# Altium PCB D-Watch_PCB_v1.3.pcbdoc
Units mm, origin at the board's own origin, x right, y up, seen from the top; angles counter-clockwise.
Board outline 59.16 x 50.57 mm, 4 copper layers (Top Layer, Inner1, Inner2, Bottom Layer); 66 components, 55 nets, 256 pads, 104 vias.
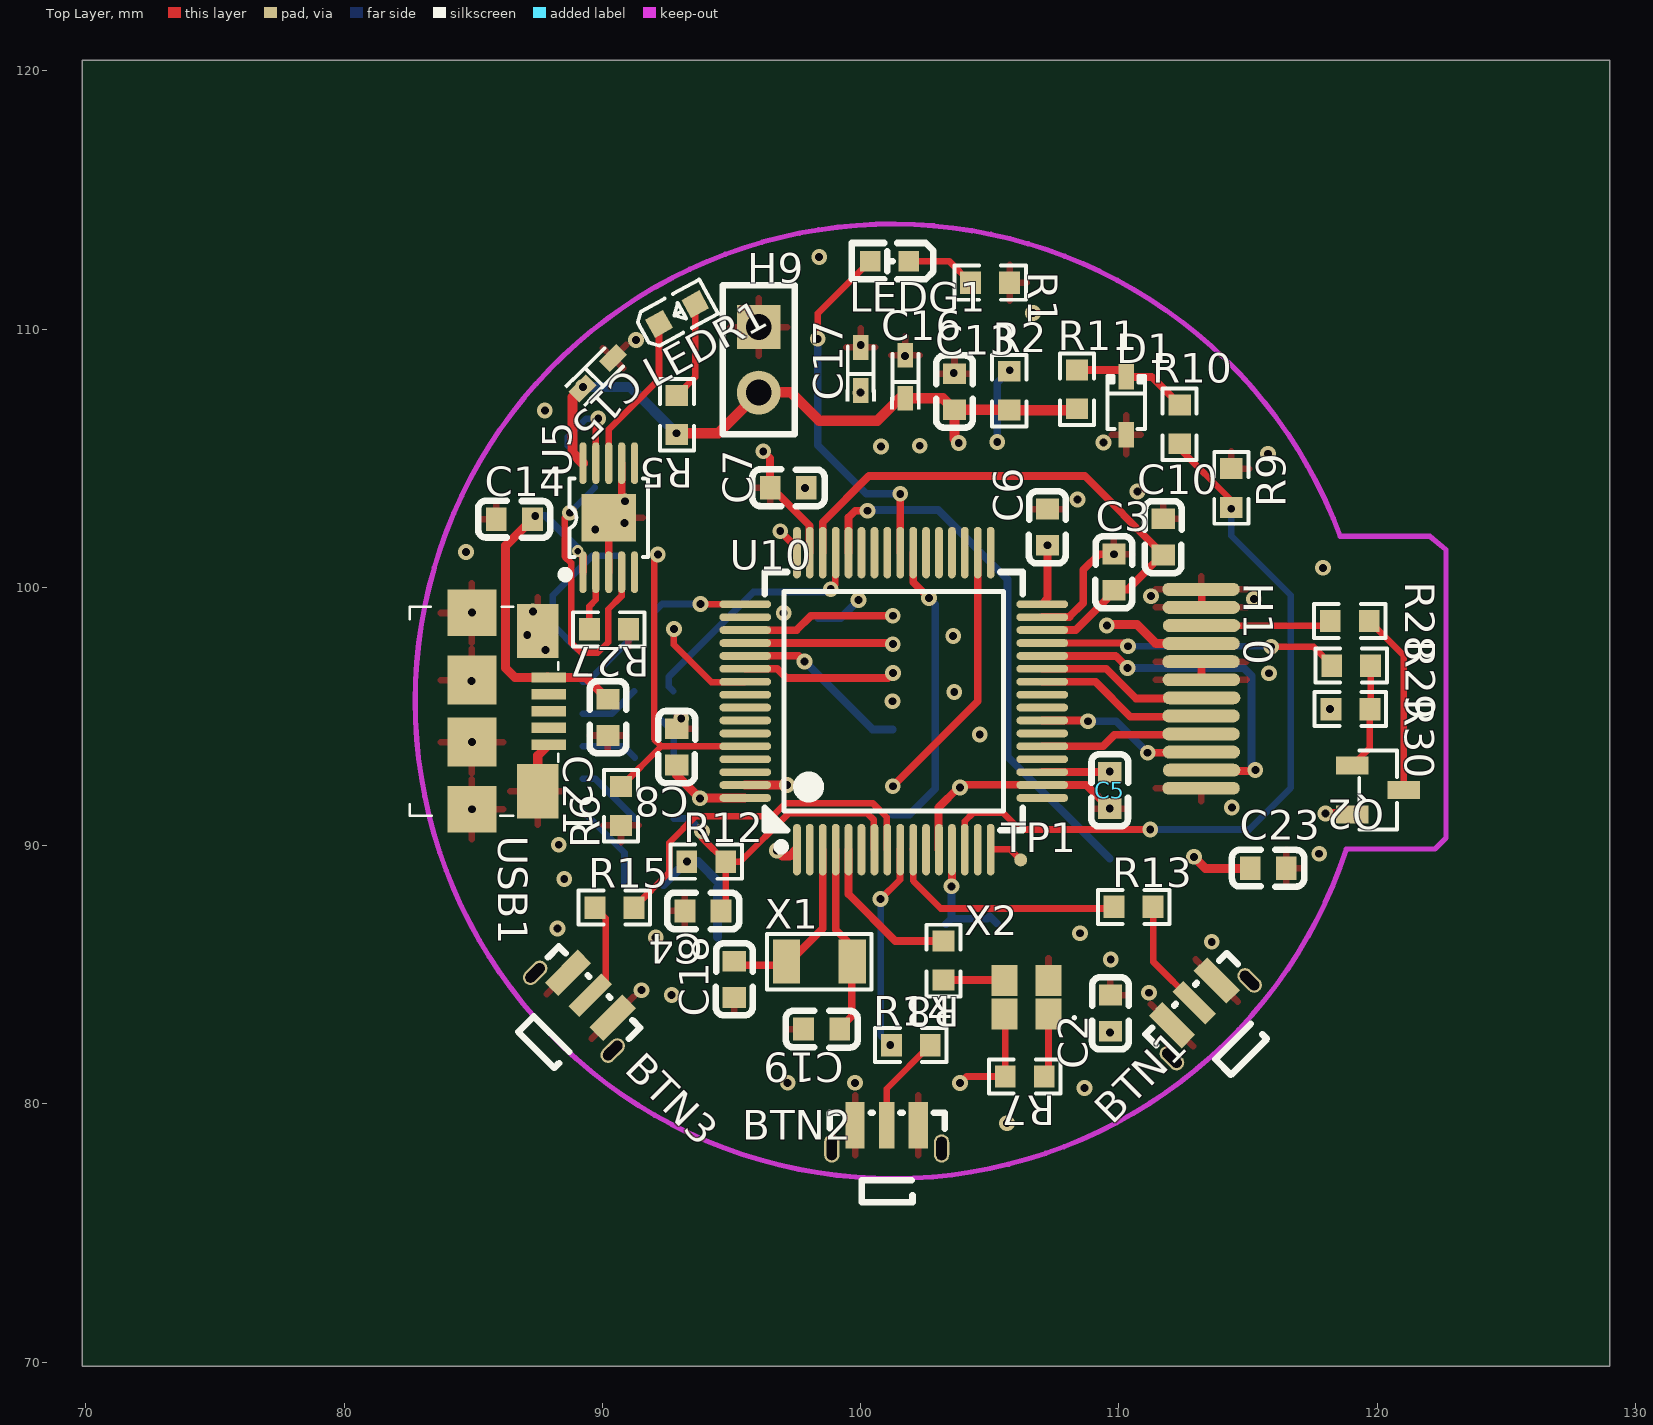
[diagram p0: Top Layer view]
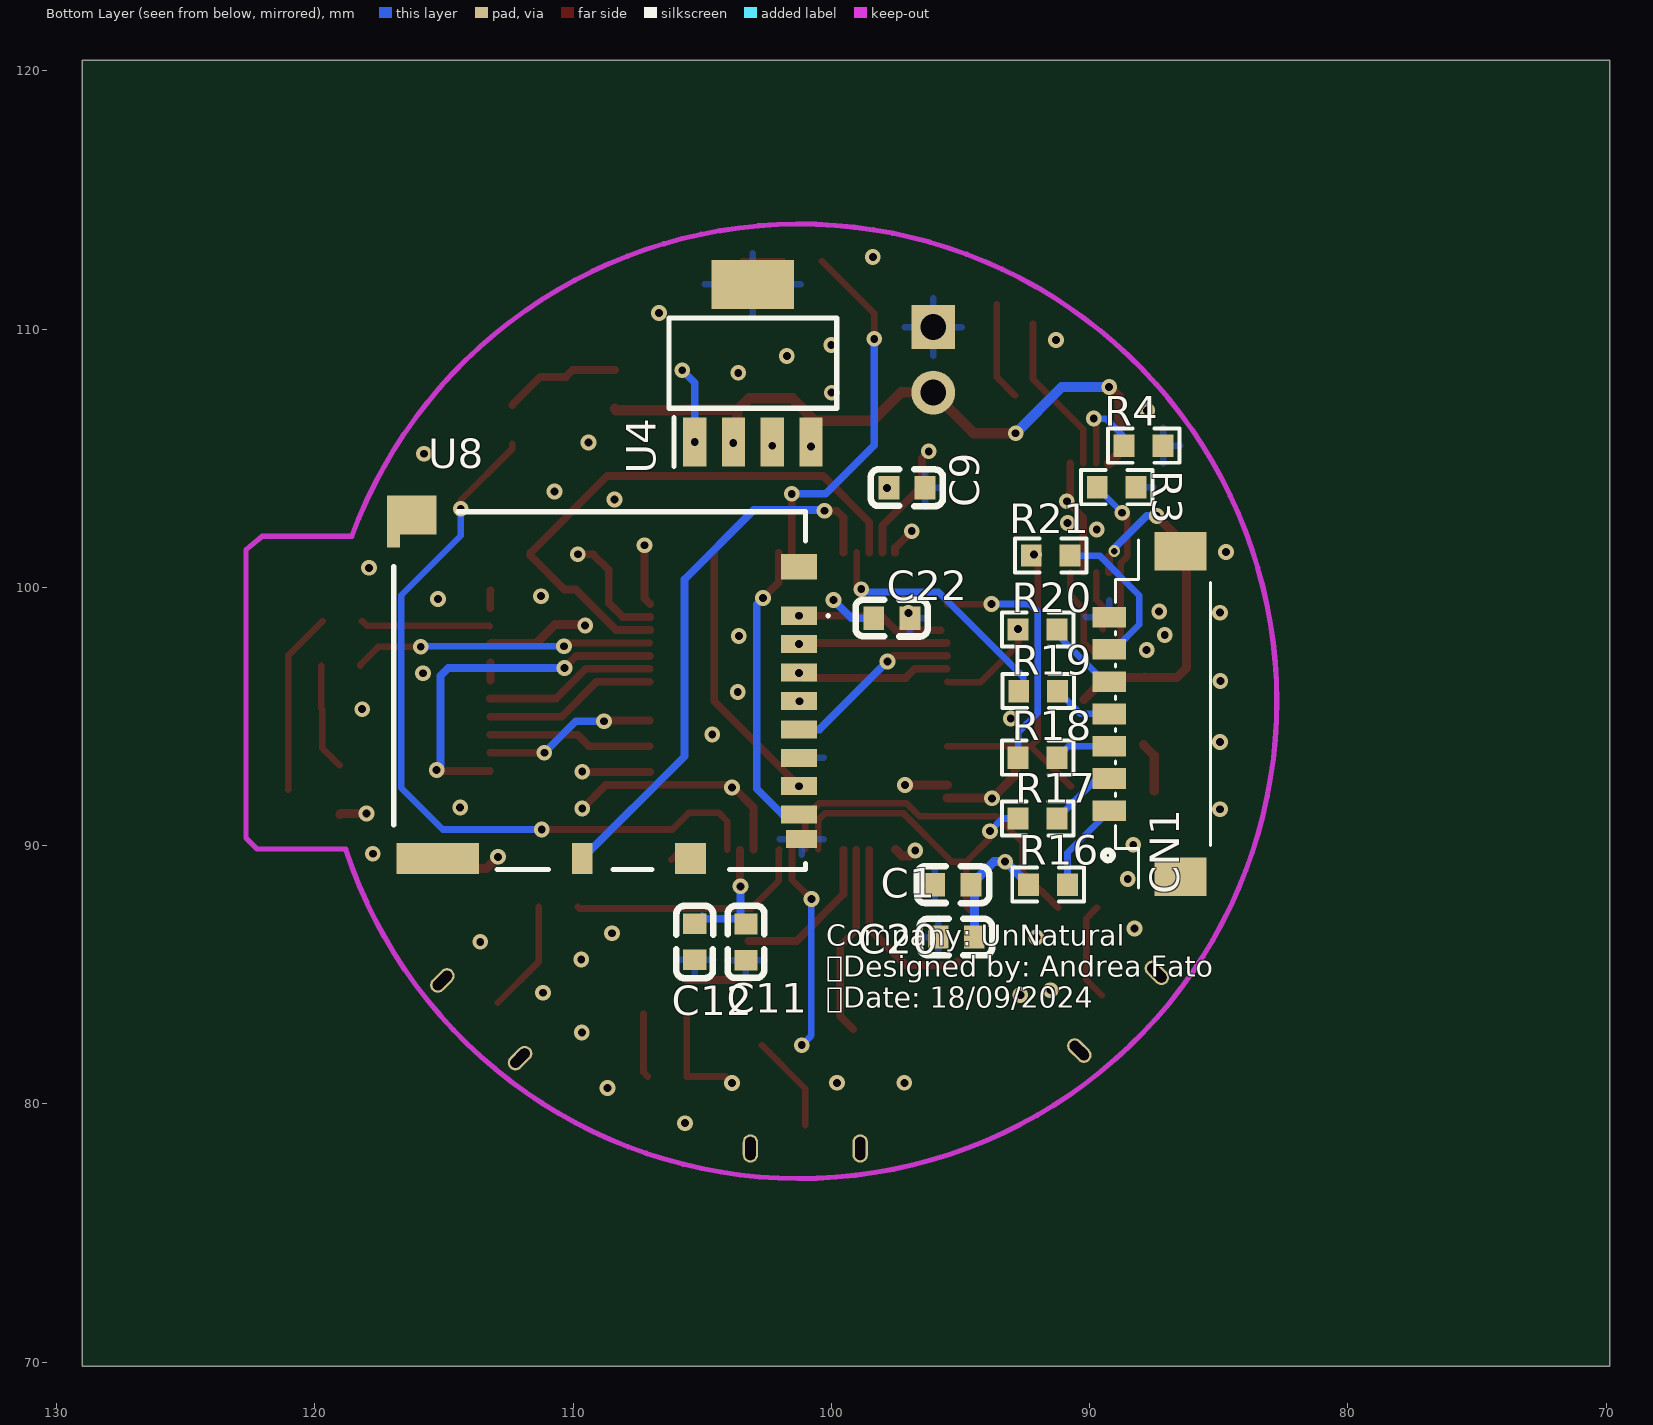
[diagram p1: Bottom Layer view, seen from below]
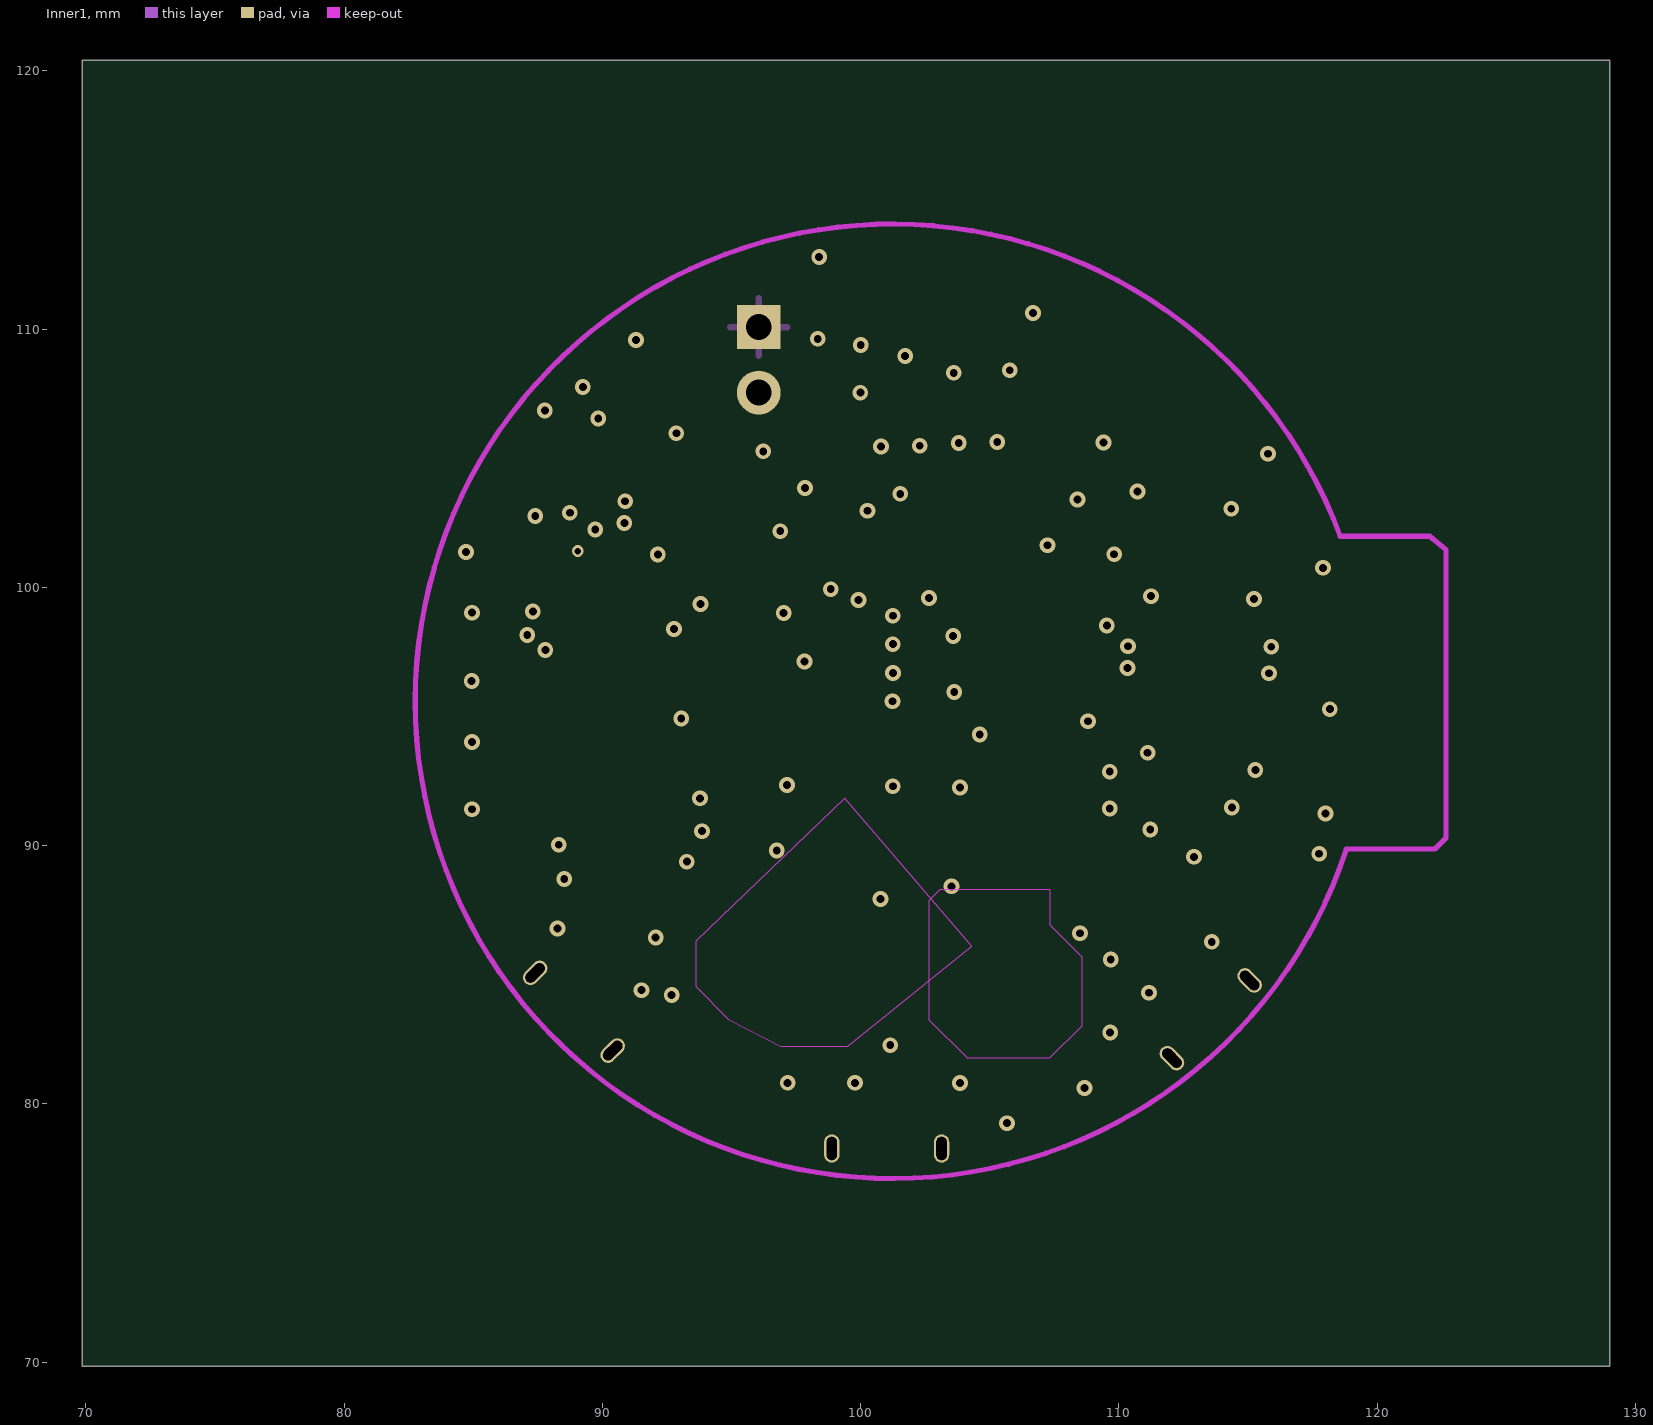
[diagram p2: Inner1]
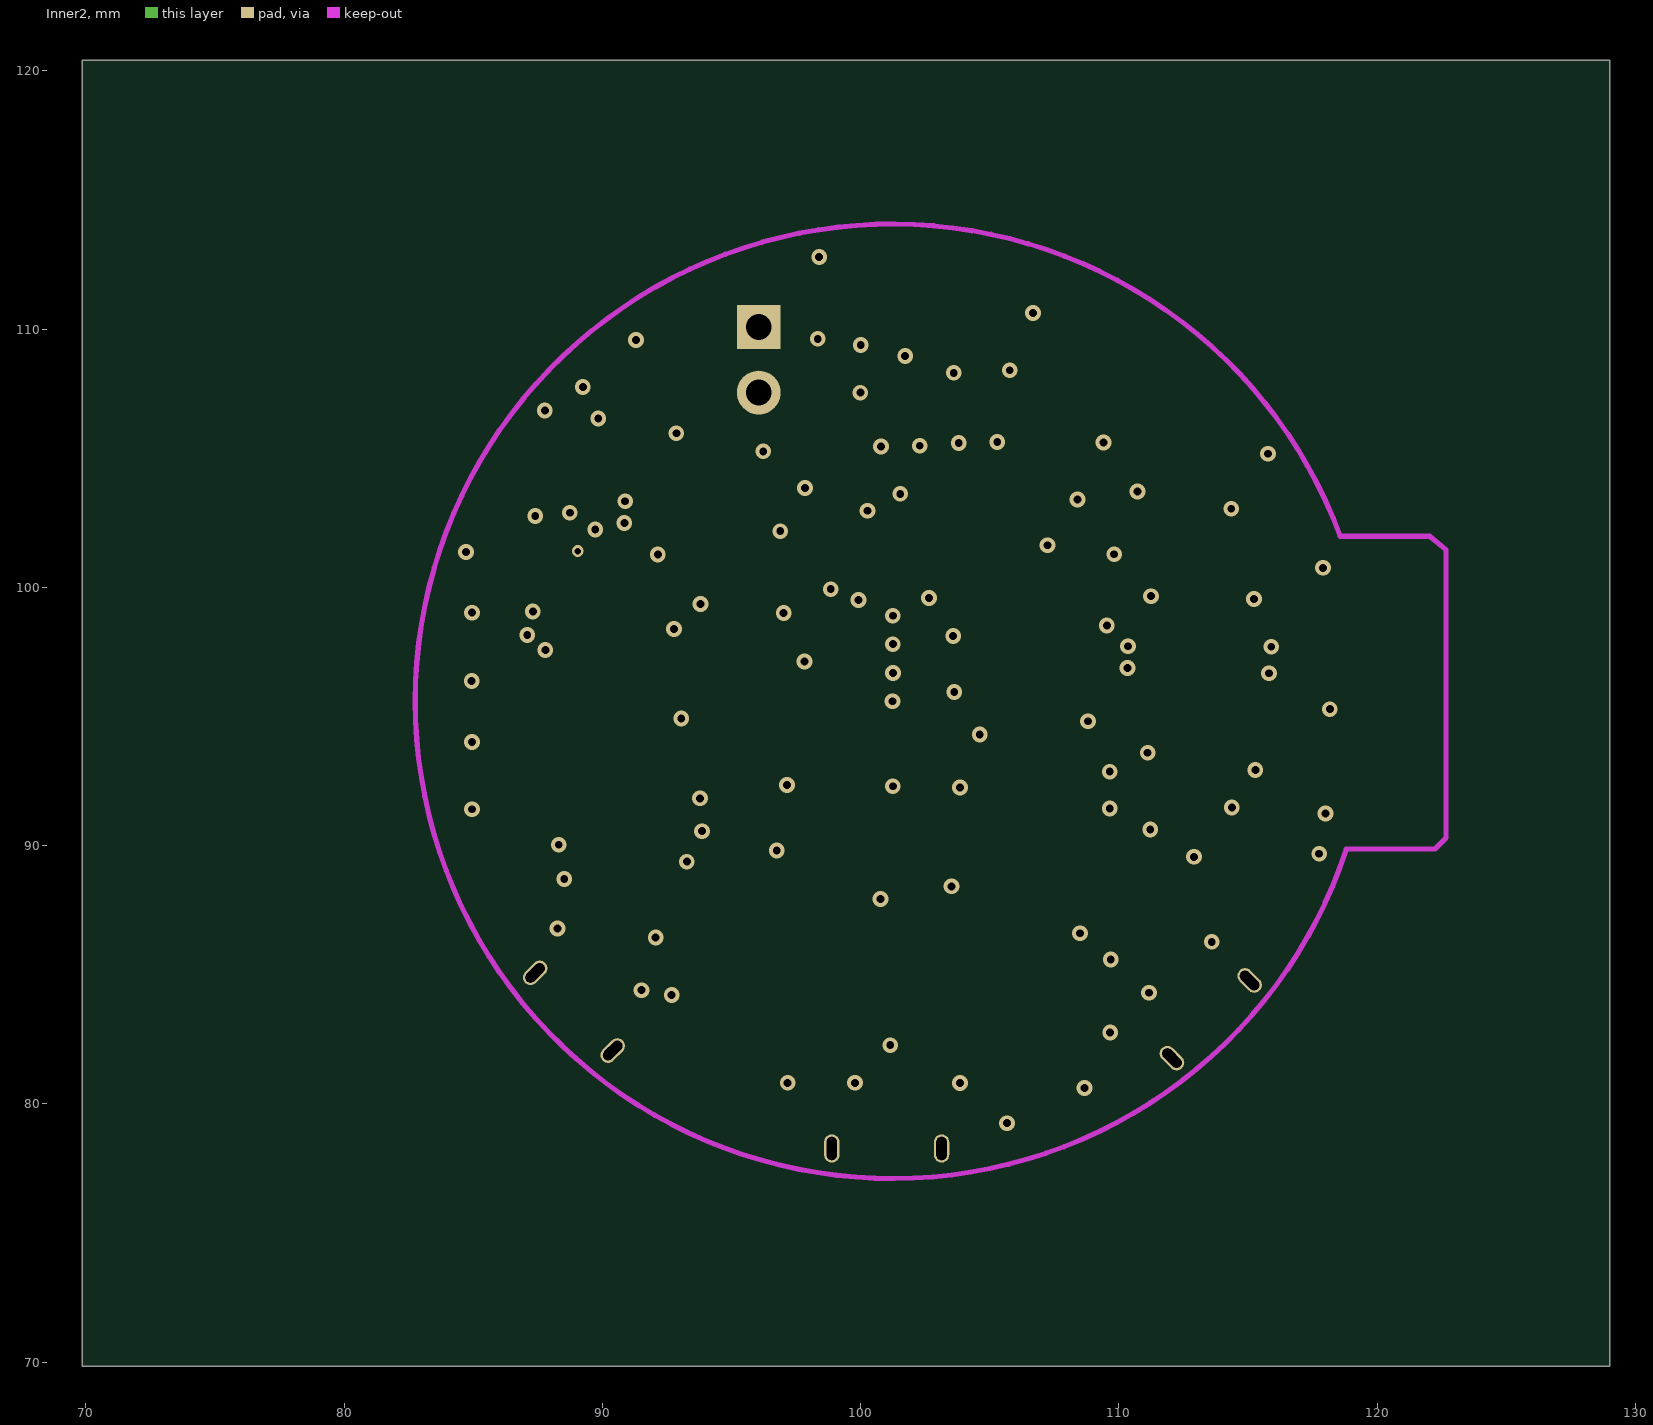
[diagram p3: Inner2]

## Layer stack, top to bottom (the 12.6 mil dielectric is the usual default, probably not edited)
Top Layer: signal copper (thickness not stored)
Dielectric: dielectric 0.32, FR-4, Dk 4.8
Inner1: signal copper (thickness not stored)
Dielectric: dielectric 0.32, FR-4, Dk 4.8
Inner2: signal copper (thickness not stored)
Dielectric: dielectric 0.32, FR-4, Dk 4.8
Bottom Layer: signal copper (thickness not stored)

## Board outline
129.01,69.85 69.85,69.85 69.85,120.418 129.01,120.418

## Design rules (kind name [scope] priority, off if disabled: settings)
Clearance copperThickness1oz [All] p1: gap=0.178 ignorepadtopadclearanceinfootprint=FALSE except(0.01: SMDPad-SMDPad; 0.102: Track-Track; 0.152: Track-SMDPad Track-THPad SMDPad-THPad THPad-THPad Track-Via SMDPad-Via THPad-Via Via-Via Track-Fill SMDPad-Fill THPad-Fill Via-Fill Fill-Fill SMDPad-Region THPad-Region Via-Region Fill-Region Region-Region Track-Poly SMDPad-Poly THPad-Poly Via-Poly Fill-Poly Poly-Poly Track-Text SMDPad-Text THPad-Text Via-Text Fill-Text Region-Text Poly-Text Text-Text; 0.175: Track-Hole SMDPad-Hole THPad-Hole Via-Hole Fill-Hole Region-Hole Poly-Hole Text-Hole Sheet-Hole; 0.3: Track-Region Region-Poly Track-Sheet SMDPad-Sheet THPad-Sheet Via-Sheet Fill-Sheet Region-Sheet Poly-Sheet Text-Sheet)
Clearance copperThickness2oz [All] p1: gap=0.178 ignorepadtopadclearanceinfootprint=FALSE except(0.152: Track-SMDPad SMDPad-SMDPad Track-THPad SMDPad-THPad THPad-THPad Track-Via SMDPad-Via THPad-Via Via-Via SMDPad-Fill THPad-Fill Via-Fill Fill-Fill Track-Region SMDPad-Region THPad-Region Via-Region Region-Region Track-Poly SMDPad-Poly THPad-Poly Via-Poly Fill-Poly Region-Poly Poly-Poly Track-Text SMDPad-Text THPad-Text Via-Text Fill-Text Region-Text Poly-Text Text-Text; 0.175: Track-Hole SMDPad-Hole THPad-Hole Via-Hole Fill-Hole Region-Hole Poly-Hole Text-Hole Sheet-Hole; 0.203: Track-Track; 0.3: Track-Fill Fill-Region Track-Sheet SMDPad-Sheet THPad-Sheet Via-Sheet Fill-Sheet Region-Sheet Poly-Sheet Text-Sheet)
Clearance BGA [All] p1: gap=0.178 ignorepadtopadclearanceinfootprint=FALSE except(0.099: Track-Track Track-SMDPad SMDPad-SMDPad Track-THPad SMDPad-THPad THPad-THPad Track-Via SMDPad-Via THPad-Via Via-Via Track-Fill SMDPad-Fill THPad-Fill Via-Fill Fill-Fill Track-Region SMDPad-Region THPad-Region Via-Region Fill-Region Region-Region Track-Poly SMDPad-Poly THPad-Poly Via-Poly Fill-Poly Region-Poly Poly-Poly Track-Hole SMDPad-Hole THPad-Hole Via-Hole Fill-Hole Region-Hole Poly-Hole Text-Hole Sheet-Hole; 0.152: Track-Text SMDPad-Text THPad-Text Via-Text Fill-Text Region-Text Poly-Text Text-Text; 0.3: Track-Sheet SMDPad-Sheet THPad-Sheet Via-Sheet Fill-Sheet Region-Sheet Poly-Sheet Text-Sheet)
DiffPairsRouting differentialPair [All] p1: maxuncoupledlength=10 maxlimit=5.9843 mostfreqgap=5.9843 toplayer_minwidth=5 toplayer_prefwidth=10 toplayer_maxwidth=100 bottomlayer_minwidth=5 bottomlayer_prefwidth=10 bottomlayer_maxwidth=100 midlayer1_minwidth=5 midlayer1_prefwidth=10 midlayer1_maxwidth=100 midlayer2_minwidth=5 midlayer2_prefwidth=10 midlayer2_maxwidth=100
PasteMaskExpansion pasteMaskExpansion [All] p1:
PlaneConnect innerPlane [All] p1: planeconnectstyle=Relief reliefexpansion=0.508 reliefentries=4 reliefconductorwidth=0.254 reliefairgap=0.254
PolygonConnect copperRegion [All] p1: connectstyle=Relief reliefentries=4 reliefconductorwidth=10 polygonreliefangle="90 Angle" airgapwidth=10
PolygonConnect copperRegionOSC [All] p1: connectstyle=Relief reliefentries=4 reliefconductorwidth=10 polygonreliefangle="90 Angle" airgapwidth=10
RoutingVias viaSize [All] p1: viastyle="Through Hole" holewidth=12.0078 minholewidth=5.9056 maxholewidth=248.0314 width=24.0158 minwidth=9.8426 maxwidth=393.7008
SolderMaskExpansion solderMaskExpansion [All] p1: useseparateexpansions=TRUE expansion=2.0079 expansionbottom=2.0079
Width copperThickness1oz [All] p1: maxlimit=100 minlimit=4 preferedwidth=10
Width copperThickness2oz [All] p1: maxlimit=100 minlimit=8 preferedwidth=10

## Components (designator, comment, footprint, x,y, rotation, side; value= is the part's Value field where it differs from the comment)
BTN1 "436333033816" SW-SMD_436333033816 113.677,83.153 r45 top
BTN2 "436333033816" SW-SMD_436333033816 101.005,78.1 r0 top
BTN3 "436333033816" SW-SMD_436333033816 88.77,83.446 r315 top
C1 "GCJ188R71C104KA01D" C0603 95.29,88.49 r0 bottom
C2 "GCJ188R71C104KA01D" C0603 109.67,83.516 r90 top
C3 "GCJ188R71C104KA01D" C0603 109.803,100.59 r90 top
C4 "GCJ188R71C104KA01D" C0603 93.893,87.474 r180 top
C5 "GCJ188R71C104KA01D" C0603 109.64,92.136 r270 top
C6 "GCJ188R71C104KA01D" C0603 107.228,102.333 r90 top
C7 "GCJ188R71C104KA01D" C0603 97.195,103.857 r180 top
C8 "GCJ188R71C104KA01D" C0603 92.877,93.824 r90 top
C9 "GCJ188C70J475KE02D" C0603 97.068,103.857 r180 bottom
C10 "GCJ188R71C104KA01D" C0603 111.713,101.952 r90 top
C11 "GCJ188R71C104KA01D" C0603 103.306,86.267 r270 bottom
C12 "CC0603KRX7R5BB105" C0603 105.286,86.277 r90 bottom
C13 "CC0603KRX7R5BB105" C0603 103.63,107.576 r270 top
C14 "CC0603KRX7R5BB105" C0603 86.59,102.636 r0 top
C15 "T58MM106M6R3C0300" CAP-SMD_L1.6-W0.8-RD 89.82,108.286 r225 top
C16 "T58MM106M6R3C0300" CAP-SMD_L1.6-W0.8-RD 101.73,108.156 r270 top
C17 "T58MM106M6R3C0300" CAP-SMD_L1.6-W0.8-RD 100,108.456 r270 top
C18 "CAP_0603" C0603 95.104,84.819 r270 top
C19 "CAP_0603" C0603 98.484,82.898 r180 top
C20 "AC0603KRX7R6BB105" C0603 95.163,86.458 r180 bottom
C21 "GCJ188R71C104KA01D" C0603 90.21,94.966 r270 top
C22 "GCJ188R71C104KA01D" C0603 97.655,98.809 r180 bottom
C23 "GCJ188R71C104KA01D" C0603 115.779,89.124 r0 top
CN1 "53398-0771" CONN-SMD_7P-P1.25_53398-0771 87.855,95.099 r90 bottom
D1 "TDZ3V6J,115" SOD-323_L1.7-W1.3-LS2.5-RD-1 110.276,107.032 r270 top
H9 "HDR-F_2.54_1x2P" HDR-TH_2P-P2.54-V-F 96.052,108.81 r270 top
H10 "HDR-M_2.54_1x12P" HDR-TH_12P-P2.54-V-M 113.118,96.046 r270 top
LEDG1 "APT1608MGC" LED-SMD_L1.6-W0.8-RD 101.115,112.634 r180 top
LEDR1 "APT1608SURCK" LED0603-RD 92.89,110.586 r28.78 top
Q2 "NSS40200LT1G" SOT-23-3_L2.9-W1.3-P1.90-LS2.4-BR 120.03,92.156 r180 top
R1 "Res_0603" R0603 105.01,111.797 r180 top
R2 "Res_0603" R0603 105.75,107.616 r90 top
R3 "Res_0603" R0603 88.95,103.879 r0 bottom
R4 "Res_0603" R0603 87.907,105.487 r180 bottom
R5 "Res_0603" R0603 92.881,106.678 r90 top
R6 "Res_0603" R0603 90.718,91.538 r90 top
R7 "Res_0603" R0603 106.35,81.063 r180 top
R8 "Res_0603" R0603 103.207,85.553 r90 top
R9 "Res_0603" R0603 114.349,103.848 r90 top
R10 "Res_0603" R0603 112.347,106.311 r90 top
R11 "Res_0603" R0603 108.371,107.667 r270 top
R12 "Res_0603" R0603 94.02,89.379 r0 top
R13 "Res_0603" R0603 110.566,87.629 r180 top
R14 "Res_0603" R0603 101.94,82.276 r180 top
R15 "Res_0603" R0603 90.464,87.601 r0 top
R16 "Res_0603" R0603 91.607,88.49 r180 bottom
R17 "Res_0603" R0603 92.012,91.051 r180 bottom
R18 "Res_0603" R0603 92.012,93.405 r180 bottom
R19 "Res_0603" R0603 91.988,95.983 r180 bottom
R20 "Res_0603" R0603 92.012,98.368 r180 bottom
R21 "Res_0603" R0603 91.504,101.231 r180 bottom
R27 "Res_0603" R0603 90.25,98.376 r180 top
R28 "Res_0603" R0603 118.935,98.695 r180 top
R29 "Res_0603" R0603 118.99,96.972 r180 top
R30 "Res_0603" R0603 118.96,95.286 r0 top
TP1 "Test-Point" Test-Point-0.5mm 106.194,89.448 r0 top
U4 "LP3874EMP-3.3_NOPB_" SOT150P700X180-5N 103.037,108.683 r90 bottom
U5 "BQ24092DGQR" MSOP-10_L3.0-W3.0-P0.50-LS5.0-BL-EP 90.244,102.699 r0 top
U8 "DM3BT-DSF-PEJS_" DM3BTDSFPEJS 108.869,96.227 r270 bottom
U10 "STM32H7B0RBT6" LQFP-64_L10.0-W10.0-P0.50-LS12.0-BL 101.28,95.596 r0 top
USB1 "10118192-0001LF" MICRO-USB-SMD_10118192-0001LF_1 86.432,95.209 r270 top
X1 "NX3215SA-32.768K-STD-MUA-9" CRYSTAL-SMD_L3.2-W1.5-1 98.395,85.507 r0 top
X2 "EC5625ETTTS-25.000M_TR_" EC5625ETTTS25000MTR 106.42,84.136 r180 top

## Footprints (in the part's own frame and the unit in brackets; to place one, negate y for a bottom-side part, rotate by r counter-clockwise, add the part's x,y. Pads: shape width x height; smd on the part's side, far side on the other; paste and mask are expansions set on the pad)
C0603 [mm]
  rect 0.8x0.9 smd: 1(-0.7,0) 2(0.7,0)
  silkscreen extent -1.41,-0.71 1.39,0.72
CAP-SMD_L1.6-W0.8-RD [mm]
  rect 0.954x0.594 smd: 1(0.835,0) 2(-0.835,0)
  silkscreen extent -0.88,-0.58 1.26,0.58
CONN-SMD_7P-P1.25_53398-0771 [mm]
  rect 0.8x1.3 smd: 1(-3.75,1.375) 2(-2.5,1.375) 3(-1.25,1.375) 4(0,1.375) 5(1.25,1.375) 6(2.5,1.375) 7(3.75,1.375)
  rect 1.5x2 smd: 8(6.3,-1.375) 9(-6.3,-1.375)
  silkscreen extent -6.73,-2.54 6.73,1.61
CRYSTAL-SMD_L3.2-W1.5-1 [mm]
  rect 1.05x1.7 smd: 1(-1.275,0) 2(1.275,0)
  silkscreen extent -2.03,-1.08 2.03,1.08
DM3BTDSFPEJS [mm]
  rect 0.7x1.4 smd: 1(-2.675,7.625) 2(-1.575,7.625) 3(-0.475,7.625) 4(0.625,7.625) 5(1.725,7.625) 6(2.825,7.625) 7(3.925,7.625) 8(5.025,7.625)
  rect 1.2x0.8 smd: 9(6.725,-0.775)
  rect 0.7x1.2 smd: 10(5.975,7.725)
  rect 1x1.4 smd: 11(-4.575,7.625)
  rect 1.2x1.2 smd: 12(6.725,3.425)
  rect 1.2x3.2 smd: 13(6.725,-6.375)
  rect 1.5x1.9 smd: 14(-6.575,-7.375)
  rect 0.5x0.5 smd: 15(-5.575,-8.075)
  silkscreen extent -6.7,-8.07 7.15,8.8
EC5625ETTTS25000MTR [mm]
  rect 1x1.2 smd: 1(-0.85,0.65) 2(-0.85,-0.65) 3(0.85,-0.65) 4(0.85,0.65)
  silkscreen extent -1.9,0.75 -1.8,0.85
HDR-TH_2P-P2.54-V-F [mm]
  rect 1.7x1.7 hole 1: 1(-1.27,0)
  round 1.7 hole 1: 2(1.27,0)
  silkscreen extent -2.88,-1.39 2.88,1.4
HDR-TH_12P-P2.54-V-M [mm]
  oval 0.5x3 smd: 1(-3.877,0.059) 2(-3.177,0.069) 3(-2.477,0.079) 4(-1.777,0.059) 5(-1.077,0.059) 6(-0.377,0.069) 7(0.323,0.079) 8(1.023,0.059) 9(1.723,0.059) 10(2.423,0.069) 11(3.123,0.079) 12(3.823,0.059)
LED0603-RD [mm]
  rect 0.8x0.8 smd: 1(-0.799,0) 2(0.799,0)
  silkscreen extent -1.49,-0.75 1.39,0.76
LED-SMD_L1.6-W0.8-RD [mm]
  rect 0.8x0.8 smd: 1(-0.75,0) 2(0.75,0)
  silkscreen extent -1.7,-0.7 1.47,0.7
LQFP-64_L10.0-W10.0-P0.50-LS12.0-BL [mm]
  oval 0.3x2 smd: 1(-3.75,-5.75) 2(-3.25,-5.75) 3(-2.75,-5.75) 4(-2.25,-5.75) 5(-1.75,-5.75) 6(-1.25,-5.75) 7(-0.75,-5.75) 8(-0.25,-5.75) 9(0.25,-5.75) 10(0.75,-5.75) 11(1.25,-5.75) 12(1.75,-5.75) 13(2.25,-5.75) 14(2.75,-5.75) 15(3.25,-5.75) 16(3.75,-5.75) 33(3.75,5.75) 34(3.25,5.75) 35(2.75,5.75) 36(2.25,5.75) 37(1.75,5.75) 38(1.25,5.75) 39(0.75,5.75) 40(0.25,5.75) 41(-0.25,5.75) 42(-0.75,5.75) 43(-1.25,5.75) 44(-1.75,5.75) 45(-2.25,5.75) 46(-2.75,5.75) 47(-3.25,5.75) 48(-3.75,5.75)
  oval 2x0.3 smd: 17(5.75,-3.75) 18(5.75,-3.25) 19(5.75,-2.75) 20(5.75,-2.25) 21(5.75,-1.75) 22(5.75,-1.25) 23(5.75,-0.75) 24(5.75,-0.25) 25(5.75,0.25) 26(5.75,0.75) 27(5.75,1.25) 28(5.75,1.75) 29(5.75,2.25) 30(5.75,2.75) 31(5.75,3.25) 32(5.75,3.75) 49(-5.75,3.75) 50(-5.75,3.25) 51(-5.75,2.75) 52(-5.75,2.25) 53(-5.75,1.75) 54(-5.75,1.25) 55(-5.75,0.75) 56(-5.75,0.25) 57(-5.75,-0.25) 58(-5.75,-0.75) 59(-5.75,-1.25) 60(-5.75,-1.75) 61(-5.75,-2.25) 62(-5.75,-2.75) 63(-5.75,-3.25) 64(-5.75,-3.75)
  silkscreen extent -5,-5.79 5,5
MICRO-USB-SMD_10118192-0001LF_1 [mm]
  rect 0.4x1.35 smd: 1(-1.3,1.487) 2(-0.65,1.487) 3(0,1.487) 4(0.65,1.487) 5(1.3,1.487)
  rect 1.8x1.9 smd: 6(-3.8,-1.487) 6(3.8,-1.487)
  rect 2.1x1.6 smd: 6(-3.1,1.063) 6(3.1,1.063)
  rect 1.9x1.9 smd: 6(-1.199,-1.487) 6(1.199,-1.487)
  silkscreen extent -4.05,-3.89 4.05,1.86
MSOP-10_L3.0-W3.0-P0.50-LS5.0-BL-EP [mm]
  oval 0.28x1.62 smd: 1(-1,-2.11) 2(-0.5,-2.11) 3(0,-2.11) 4(0.5,-2.11) 5(1,-2.11) 6(1,2.11) 7(0.5,2.11) 8(0,2.11) 9(-0.5,2.11) 10(-1,2.11)
  rect 2.1x1.83 smd: 11(0,0)
  silkscreen extent -1.84,-2.35 1.52,1.52
R0603 [mm]
  rect 0.806x0.864 smd: 1(-0.753,0) 2(0.753,0)
  silkscreen extent -1.39,-0.66 1.39,0.66
SOD-323_L1.7-W1.3-LS2.5-RD-1 [mm]
  rect 0.985x0.6 smd: 1(-1.118,0) 2(1.118,0)
  silkscreen extent -1.15,-0.73 0.9,0.73
SOT150P700X180-5N [mm]
  rect 1.9x0.9 smd: 1(-3.05,2.25) 2(-3.05,0.75) 3(-3.05,-0.75) 4(-3.05,-2.25)
  rect 1.9x3.2 smd: 5(3.05,0)
  silkscreen extent -4,-3.25 1.75,3.25
SOT-23-3_L2.9-W1.3-P1.90-LS2.4-BR [mm]
  rect 1.25x0.7 smd: 1(1,-0.95) 2(1,0.95) 3(-1,0)
  silkscreen extent -0.73,-1.53 0.73,1.53
SW-SMD_436333033816 [mm]
  rect 0.75x1.8 smd: 1(-1.225,1.075) 3(1.225,1.075)
  rect 0.6x1.8 smd: 2(0,1.075)
  oval 0.6x1.1 hole 0.4 slot 0.9 at 90 deg: 6(-2.125,0.175) 6(2.125,0.175)
  silkscreen extent -2.2,-1.9 2.25,1.55
Test-Point-0.5mm [mm]
  round 0.5 smd: 1(0,0)

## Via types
v1: diameter 0.61, hole 0.305, Top Layer to Bottom Layer, 103 vias
v2: diameter 0.45, hole 0.25, Top Layer to Bottom Layer, 1 vias

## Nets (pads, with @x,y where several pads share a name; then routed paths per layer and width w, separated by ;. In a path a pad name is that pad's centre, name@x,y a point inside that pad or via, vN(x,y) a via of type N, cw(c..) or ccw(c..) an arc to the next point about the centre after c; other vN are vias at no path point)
5V_USB_CHGR: C14.2 C21.1 U5.1 USB1.1 | length 14
  Top Layer w0.3: v2(89.038,101.407) 89.244,101.201 U5.1
  Top Layer w0.35: v1(87.396,102.762) 86.25,101.616 86.25,96.876 86.617,96.509 87.858,96.509 USB1.1@87.87,96.521 ; USB1.1 89.367,96.509 C21.1
  Bottom Layer w0.3: v1(87.396,102.762) 87.41,102.776 87.78,102.776 89.038,101.518 v2(89.038,101.407)
$1N5489: R2.2 U4.1 | length 3
  Bottom Layer w0.3: v1(105.287,105.633) 105.287,107.926 v1(105.77,108.409)
$1N5967: R3.2 U5.4 | length 11.3
  Top Layer w0.254: v1(88.737,102.89) 88.534,102.687 88.534,101.198 88.788,100.944 88.788,97.855 89.177,97.466 89.816,97.466 90.224,97.874 90.224,99.15 90.74,99.666 90.74,100.585 U5.4
  Bottom Layer w0.254: v1(88.737,102.89) 89.704,103.857 R3.2
$1N5968: R27.2 U5.2 | length 2.3
  Top Layer w0.254: R27.2 89.497,99.272 89.744,99.52 U5.2
$1N5969: R4.1 U5.9 | length 3.6
  Top Layer w0.254: U5.9 89.744,106.443 v1(89.837,106.536)
  Bottom Layer w0.254: R4.1 88.661,105.826 89.37,106.536 v1(89.837,106.536)
$1N5973: LEDR1.1 U5.8 | length 6.2
  Top Layer w0.254: U5.8 90.244,106.117 92.189,108.062 LEDR1.1
$1N5974: LEDR1.2 R5.2 | length 3.8
  Top Layer w0.254: R5.2 93.591,108.141 LEDR1.2
$1N21382: LEDG1.1 R1.2 | length 2.7
  Top Layer w0.254: LEDG1.1 103.42,112.634 R1.2
$2N8217: R7.1 X2.1 | length 2.5
  Top Layer w0.254: R7.1 107.27,81.229 X2.1
$2N8264: R8.1 X2.3 | length 2.4
  Top Layer w0.3: R8.1 105.557,84.799 X2.3
$2N18890: D1.1 R10.2 R11.1 | length 4.5
  Top Layer w0.3: R11.1 110.005,108.42 D1.1 111.262,108.15 R10.2
$2N23973: TP1.1 U10.16 | length 1.4
  Top Layer w0.254: U10.16@105.009,89.852 105.789,89.852 TP1.1
$3N1058: CN1.1 R16.2 | length 3.5
  Bottom Layer w0.254: CN1.1 90.854,89.725 R16.2
$3N1061: CN1.2 R17.2 | length 2.7
  Bottom Layer w0.254: CN1.2 89.711,92.599 R17.2
$3N1065: CN1.3 R18.2 | length 2.2
  Bottom Layer w0.254: CN1.3 90.815,93.849 R18.2
$3N1094: CN1.4 R19.2 | length 2.4
  Bottom Layer w0.254: CN1.4 90.35,95.099 R19.2
$3N1097: CN1.5 R20.2 | length 3
  Bottom Layer w0.254: CN1.5 89.425,96.349 91.259,98.182 R20.2
$3N1126: CN1.6 R21.2 | length 6
  Bottom Layer w0.254: CN1.6 89.036,97.599 88.08,98.554 88.08,99.696 89.615,101.231 R21.2
$3N2256: BTN2.2 R14.1 | length 3.8
  Top Layer w0.254: BTN2.2 101.005,80.588 R14.1
$3N2358: BTN3.2 R15.1 | length 3.8
  Top Layer w0.254: BTN3.2 90.13,84.806 90.13,87.182 R15.1
$3N11256: BTN1.2 R13.1 | length 4.4
  Top Layer w0.254: R13.1 111.319,85.511 BTN1.2
$3N22100: H10.3 R28.2 | length 5
  Top Layer w0.254: H10.3@113.219,98.493 113.239,98.513 117.979,98.513 118.162,98.695 R28.2
$3N22908: Q2.1 R29.1 R30.2 | length 4.2
  Top Layer w0.254: Q2.1 119.713,93.789 R30.2 119.743,95.316 R29.1
$3N22933: Q2.3 R28.1 | length 7.1
  Top Layer w0.254: R28.1 121.03,97.354 Q2.3
+3V3: 
ADC1_IN16: R9.1 R10.1 U10.14 | length 29.9
  Top Layer w0.254: U10.14 104.03,90.946 104.35,91.266 105.52,91.266 106.16,90.626 v1(111.21,90.626) ; R10.1 112.347,105.374 114.349,103.372 v1(114.349,103.045)
  Bottom Layer w0.254: v1(111.21,90.626) 115.04,90.626 116.65,92.236 116.65,99.696 114.349,101.997 v1(114.349,103.045)
BOOT0: R6.2 R21.1 U10.60 | length 13
  Top Layer w0.254: R6.2 92.279,93.852 ; v1(92.144,101.271) 92,101.127 92,94.131 92.279,93.852 ; U10.60@95.509,93.852 93.45,93.852 93.443,93.845 92.312,93.845 92.305,93.852 92.279,93.852
GC9A01_BL: R29.2 U10.29 | length 11.6
  Top Layer w0.254: U10.29 110.227,97.846 v1(110.353,97.719) ; v1(115.894,97.702) 117.533,97.702 118.237,96.999 R29.2
  Bottom Layer w0.254: v1(110.353,97.719) 115.877,97.719 v1(115.894,97.702)
GC9A01_CS: H10.8 U10.26 | length 6.7
  Top Layer w0.3: U10.26 109.09,96.346 110.443,94.993 H10.8@113.199,94.993
GC9A01_DC: H10.7 U10.27 | length 6.7
  Top Layer w0.3: U10.27 109.51,96.846 110.663,95.693 H10.7@113.219,95.693
GC9A01_RST: H10.11 U10.28 | length 14.2
  Top Layer w0.3: U10.28 109.868,97.346 v1(110.334,96.88) ; H10.11@113.219,92.893 115.239,92.893 v1(115.279,92.933)
  Bottom Layer w0.3: v1(110.334,96.88) 114.83,96.88 115.13,96.58 115.13,93.082 v1(115.279,92.933)
GND: BTN1.1 BTN1.3 BTN2.1 BTN2.3 BTN3.1 BTN3.3 C1.2 C2.2 C3.2 C4.2 C5.2 C6.2 C7.2 C8.2 C9.2 C10.2 C11.2 C12.1 C13.1 C14.1 C15.2 C16.2 C17.2 C18.2 C19.2 C20.1 C21.2 C22.2 C23.2 CN1.7 D1.2 H9.1 H10.1 H10.2 H10.5 H10.6 H10.12 R1.1 R3.1 R4.2 R6.1 R9.2 R27.1 U4.5 U5.3 U5.7 U5.11 U8.6 U8.10 U10.12 U10.18 U10.31 U10.47 U10.63 USB1.5 USB1.6 X2.2 | length 27.7
  Top Layer w0.3: U5.3 U5.11 90.744,103.199 U5.7 ; v1(96.225,105.267) 96.49,105.002 96.49,103.916 98.02,102.386 98.02,101.356 U10.47 ; U10.12@103.009,89.852 103.009,91.475 103.79,92.256 v1(103.84,92.256) 103.94,92.356 107.02,92.356 U10.18 ; U10.31@107.009,98.852 107.013,98.856 108.08,98.856 108.62,99.396 108.62,100.676 109.228,101.284 v1(109.813,101.284) ; U10.18@107.03,92.352 108.724,92.352 v1(109.64,91.436) ; H10.5@113.199,97.093 113.199,96.403 H10.6@113.209,96.393 ; H10.1@113.199,99.893 113.209,99.883 H10.2@113.209,99.193
  Top Layer w0.35: USB1.6@87.495,92.109 87.495,93.484 USB1.5 ; U10.63@95.509,92.352 v1(97.15,92.352)
  other v1: 105.66,79.256 97.17,80.816 99.78,80.817 92.68,84.216 111.16,84.306 91.51,84.406 109.68,85.596 113.59,86.276 92.06,86.446 108.49,86.606 88.26,86.796 88.523,88.71 117.75,89.686 88.309,90.036 84.945,91.409 114.37,91.476 84.945,94.01 104.61,94.306 93.052,94.919 103.62,95.946 84.936,96.372 115.81,96.676 87.79,97.571 103.58,98.116 87.086,98.159 84.946,99.02 97.016,99.004 87.305,99.069 115.232,99.546 111.243,99.66 117.896,100.756 84.72,101.366 89.72,102.246 90.848,102.495 90.88,103.336 108.39,103.406 110.72,103.716 115.77,105.176 109.404,105.614 87.77,106.846 103.6,108.306 101.72,108.96 100,109.386 91.3,109.576 106.67,110.626 98.39,112.796
MINUS_BTN: R13.2 U10.10 | length 9.5
  Top Layer w0.254: U10.10@102.009,89.852 102.03,89.831 102.03,88.635 103.1,87.566 109.749,87.566 R13.2
OSC32_IN: C18.1 U10.3 X1.1 | length 7.1
  Top Layer w0.3: C18.1@95.11,85.516 95.258,85.368 97.105,85.368 98.53,86.792 U10.3@98.53,89.831
OSC32_OUT: C19.1 U10.4 X1.2 | length 7.4
  Top Layer w0.3: U10.4@99.03,89.831 99.03,86.746 99.655,86.121 99.655,83.39 C19.1@99.152,82.887
OSC_25M: R8.2 U10.5 | length 6.2
  Top Layer w0.3: U10.5 99.53,88.116 101.34,86.306 R8.2
PLUS_BTN: R15.2 U10.8 | length 13.6
  Top Layer w0.254: R15.2 92.585,88.968 92.585,90.116 93.613,91.145 96.595,91.145 97.097,91.646 100.46,91.646 101.009,91.097 U10.8@101.009,89.852
PWR_STAT: LEDG1.2 U10.40 | length 14.2
  Top Layer w0.254: v1(98.335,109.624) 98.335,110.604 LEDG1.2
  Top Layer w0.3: U10.40 v1@101.53,103.623
  Bottom Layer w0.3: v1(98.335,109.624) 98.335,105.501 100.213,103.623 v1(101.53,103.623)
RESET#: C4.1 R12.2 R17.1 U10.7 | length 12.6
  Top Layer w0.254: v1(93.855,90.561) 93.855,90.297 R12.2 ; C4.1 94.774,87.654 R12.2 ; U10.7@100.509,89.852 100.509,90.993 100.255,91.247 97.201,91.247 95.333,89.379 R12.2
  Bottom Layer w0.254: R17.1 93.365,91.051 v1(93.855,90.561)
SDIO1_CLK: U8.5 U10.53 | length 6.9
  Top Layer w0.3: U10.53@95.509,97.352 97.604,97.352 v1(97.822,97.134)
  Bottom Layer w0.3: v1(97.822,97.134) 100.454,94.502 U8.5
SDIO1_CMD: U8.3 U10.54 | length 5.9
  Top Layer w0.3: U10.54 96.771,96.845 97.12,96.496 101.061,96.496 v1(101.246,96.681)
SDIO1_D0: U8.7 U10.34 | length 10.4
  Top Layer w0.3: v1(101.244,92.302) 104.53,95.588 U10.34
SDIO1_D1: U8.8 U10.39 | length 11.6
  Top Layer w0.3: U10.39 102.03,100.202 v1(102.641,99.591)
  Bottom Layer w0.3: U8.8 101.886,91.202 102.89,92.206 102.89,99.342 v1(102.641,99.591)
SDIO1_D2: U8.1 U10.51 | length 5.7
  Top Layer w0.3: U10.51@95.757,98.344 95.766,98.336 97.51,98.336 98.074,98.9 v1@101.244,98.9
  other v1: 101.244,98.902
SDIO1_D3: U8.2 U10.52 | length 5.7
  Top Layer w0.254: v1@101.2,97.846 v1(101.244,97.802)
  Top Layer w0.3: U10.52 v1@101.2,97.846
SET_BTN: R14.2 U10.9 | length 8
  Top Layer w0.254: v1(100.769,87.932) 101.52,88.683 101.52,89.841 U10.9@101.509,89.852
  Bottom Layer w0.254: v1(100.769,87.932) 100.769,82.652 v1(101.145,82.276)
SPI1_MOSI: H10.10 U10.23 | length 6.7
  Top Layer w0.3: U10.23 108.77,94.846 v1(108.8,94.816) ; v1(111.11,93.596) 113.206,93.596 H10.10@113.209,93.593
  Bottom Layer w0.3: v1(108.8,94.816) 109.89,94.816 v1(111.11,93.596)
SPI1_SCK: H10.9 U10.21 | length 6.4
  Top Layer w0.3: U10.21 109.38,93.846 109.827,94.293 H10.9@113.199,94.293
TCK/SWCLK: R18.1 U10.49 | length 9.6
  Top Layer w0.254: v1(93.8,99.356) 93.804,99.352 U10.49@95.509,99.352
  Bottom Layer w0.254: R18.1 92.765,94.381 92,95.146 92,99.046 92.31,99.356 v1(93.8,99.356)
TDO/SWO: R20.1 U10.55 | length 4
  Top Layer w0.254: v1(92.766,98.389) 92.766,97.78 94.22,96.326 95.483,96.326 U10.55@95.509,96.352
TMS/SWDIO: R19.1 U10.45 | length 9.8
  Top Layer w0.254: v1(98.841,99.932) 99.009,100.1 U10.45@99.009,101.352
  Bottom Layer w0.254: R19.1 92.572,96.153 92.572,96.547 95.846,99.822 98.731,99.822 v1(98.841,99.932)
USD_DETECT: U8.9 U10.44 | length 21.2
  Top Layer w0.3: U10.44 99.53,102.712 99.784,102.966 v1(100.263,102.966)
  Bottom Layer w0.3: v1(100.263,102.966) 100.293,102.996 103,102.996 105.68,100.316 105.68,93.465 U8.9
VBAT: C13.2 C15.1 C16.1 H9.2 R2.1 R5.1 R11.2 U4.2 U5.10 | length 26.2
  Top Layer w0.4: v1(89.24,107.758) 88.84,107.359 88.84,105.213 U5.10 ; v1(92.861,105.968) 94.48,105.968 H9.2 96.063,107.551 97.285,107.551 98.39,106.446 100.635,106.446 101.51,107.321 C16.1 103.185,107.321 C13.2 ; v1(103.797,105.593) 103.63,105.76 C13.2 ; R11.2 108.32,106.862 R2.1 105.737,106.876 C13.2
  Bottom Layer w0.4: v1(89.24,107.758) 91.071,107.758 v1(92.861,105.968)
VCAP: C3.1 C10.1 U10.30 U10.46 | length 22.2
  Top Layer w0.3: U10.46 98.53,102.526 100.32,104.316 108.67,104.316 111.642,101.344 111.642,101.22 110.341,99.92 109.894,99.92 108.326,98.352 U10.30@107.009,98.352
VDDA: C11.1 C12.2 U10.13 | length 4.9
  Top Layer w0.3: v1(103.516,88.424) 103.53,88.438 U10.13
  Bottom Layer w0.3: C11.1 C11.1@103.505,87.166 ; v1(103.516,88.424) 103.516,87.177 C11.1@103.505,87.166 ; C12.2 104.996,87.267 104.895,87.166 C11.1@103.505,87.166
pads on no net: BTN1.6 BTN2.6 BTN3.6 C1.1 C2.1 C5.1 C6.1 C7.1 C8.1 C9.1 C17.1 C20.2 C22.1 C23.1 CN1.8 CN1.9 H10.4 Q2.2 R7.2 R12.1 R16.1 R30.1 U4.3 U4.4 U5.5 U5.6 U8.4 U8.11 U8.12 U8.13 U8.14 U8.15 U10.1 U10.2 U10.6 U10.11 U10.15 U10.17 U10.19 U10.20 U10.22 U10.24 U10.25 U10.32 U10.33 U10.35 U10.36 U10.37 U10.38 U10.41 U10.42 U10.43 U10.48 U10.50 U10.56 U10.57 U10.58 U10.59 U10.61 U10.62 U10.64 USB1.2 USB1.3 USB1.4 X2.4
copper on no net: | length 29.1
  Top Layer w0.254: v1(103.84,80.806) 104.097,81.063 105.597,81.063 105.597,83.459 105.57,83.486
  Top Layer w0.3: v1(96.886,102.176) 97.53,101.532 97.53,101.346 ; 107.009,92.852 109.627,92.852 v1(109.641,92.866) ; 107.009,99.352 107.228,99.571 v1(107.228,101.633)
  Top Layer w0.35: 92.877,93.124 92.877,92.731 v1(93.776,91.832) 93.796,91.852 95.509,91.852 ; v1(96.749,89.812) 96.965,89.596 97.253,89.596 97.509,89.852 ; v1(109.53,98.526) 109.57,98.566 110.69,98.566 111.423,97.833 113.159,97.833 113.199,97.793 ; v1(112.9,89.566) 113.342,89.124 115.079,89.124 ; v1(118,91.246) 118.99,91.246 119.03,91.206
  Bottom Layer w0.3: 98.355,98.809 99.217,98.809 v1(99.915,99.507)
  Bottom Layer w0.35: 92.361,88.49 93.25,89.379 v1(93.267,89.379) 93.701,89.379 94.59,88.49 94.463,88.363 94.463,86.458
  other v1: 108.66,80.616 109.658,82.769 118.165,95.286 101.229,95.589 97.845,103.851 100.787,105.453 102.287,105.483 99.984,107.539

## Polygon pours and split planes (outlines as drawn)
GND on Inner1 (solid, remove dead copper): 119.255,95.602 ccw(c101.244,95.602) 83.232,95.602 ccw(c101.244,95.602)
no net on Inner2 (solid, remove dead copper): 119.56,95.445 ccw(c101.549,95.401) 83.538,95.445 ccw(c101.549,95.489)
GND on Bottom Layer (solid, remove dead copper, pour order 2): 119.249,95.582 ccw(c101.204,95.544) 83.158,95.582 ccw(c101.204,95.619)
GND on Top Layer (solid, remove dead copper): 119.17,95.522 ccw(c101.159,95.522) 83.148,95.522 ccw(c101.159,95.522)

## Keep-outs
Inner1:
  region: 99.381,91.835 93.603,86.306 93.603,84.559 94.877,83.286 96.91,82.226 99.499,82.226 104.291,86.095
  region: 102.64,87.86 102.64,83.266 104.12,81.786 107.32,81.786 108.57,83.036 108.57,85.684 107.34,86.914 107.34,88.286 103.066,88.286
Board Outline Layer:
  lines w0.2: 118.568,101.978 ccw(c101.229,95.589) 118.802,89.872 122.236,89.872 122.66,90.296 122.66,101.472 122.031,101.978 118.568,101.978

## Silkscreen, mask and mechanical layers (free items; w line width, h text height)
Bottom Silkscreen Layer:
  text "Company: UnNatural /  Designed by: Andrea Fato /  Date: 18/09/2024" at 100.2,83.716 h0.8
